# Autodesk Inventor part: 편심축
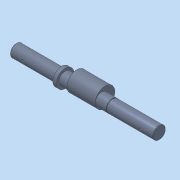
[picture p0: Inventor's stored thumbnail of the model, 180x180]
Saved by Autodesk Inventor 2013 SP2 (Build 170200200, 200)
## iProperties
Manager: 한국ATC센터
Company: 한국ATC센터
Created: 2014-10
Part Number: 편심축
Document SubType Name: Modeling
Designer: 한국ATC센터
Density: 7.86 g/cm^3
Material: 강, 연강
Mass: 1420.77 g
Surface Area: 286.546 cm^2
Volume: 180.76 cm^3
Author: KYOUNG IL JANG
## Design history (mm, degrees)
sketch "스케치1"
  geometry: L1 (-142, 0)-(142, 0); L2 (-142, 0)-(-142, 12.5); L3 (-142, 12.5)-(-52, 12.5); L4 (-52, 12.5)-(-52, 17.5); L5 (-52, 17.5)-(-45, 17.5); L6 (-45, 17.5)-(-45, 12.5); L7 (-45, 12.5)-(48.65, 12.5); L8 (48.65, 12.5)-(48.65, 11.95); L9 (48.65, 11.95)-(50, 11.95); L10 (50, 11.95)-(50, 12.5); L11 (50, 12.5)-(142, 12.5); L12 (142, 12.5)-(142, 0); L13 (109, 12.5)-(109, 9.1); L14 (109, 9.1)-(134, 9.1); L15 (134, 9.1)-(134, 12.5); L16 (117, -12.5)-(119.5, -12.5); L17 (119.5, -12.5)-(117, -10); L18 (117, -10)-(117, -12.5); L19 (-109, 12.5)-(-109, 9.1); L20 (-109, 9.1)-(-134, 9.1); L21 (-134, 9.1)-(-134, 12.5); L22 (-117, -12.5)-(-117, -10); L23 (-117, -10)-(-114.5, -12.5); L24 (-114.5, -12.5)-(-117, -12.5); 2 further points
  constraints: 48 end point, 11 parallel, 8 perpendicular, 5 collinear, 4 point on line, 1 coincident, 1 horizontal, 1 midpoint, 1 vertical
  dimensions: "d0" = 284 distance of L1.start L1.end (derived); "d1" = 25 diameter of L3 L1; "d2" = 35 diameter of L5 L1; "d3" = 90 distance of L2.end L3.end; "d4" = 187 distance between parallel lines of L12 L6; "d6" = 1.35 distance of L8.end L9.end; "d7" = 23.9 diameter of L9 L1; "d8" = 3.4 distance between parallel lines of L14 L11; "d9" = 8 distance between parallel lines of L15 L12; "d10" = 25 distance of L13.end L14.end; "d11" = 25 diameter of L16 L1 (= d1); "d12" = 25 distance from line of L12 L16.start; "d13" = 45 deg angle of L17 L18; "d14" = 5 diameter of L16.end L18; "d27" = 92 distance between parallel lines of L10 L12; "d32" = 7 distance of L4.end L5.end; "d33" = 8 distance between parallel lines of L2 L21; "d34" = 25 distance between parallel lines of L21 L19; "d35" = 3.4 distance between parallel lines of L3 L20; "d36" = 25 distance from line of L22.start L2; "d37" = 5 diameter of L23.end L22
revolve "회전1" stored, may be unused: angle "d15" = 90 deg
revolve "회전2" stored, may be unused: angle "d16" = 90 deg
revolve "회전3" stored, may be unused: angle "d38" = 90 deg
extrude "돌출1" cut sketch "스케치1" stored distance "d17" = 8; taper "d18" = 0 deg
fillet "모깎기1" dims "d19" = 4
node "작업 평면1"
sketch "스케치2"
  geometry: L1 (12.99, -6.5)-(8.66, -14); L2 (-12.99, -6.5)-(-8.66, -14); C1 r 12.5 at (0, 0) reference; C2 r 19.5 at (0, 7); A1 r 15 centre (0, 1) between (12.99, -6.5) and (-12.99, -6.5); A2 r 10 centre (0, -9) between (-8.66, -14) and (8.66, -14); 1 further point
  constraints: 5 tangent, 4 end point, 4 point on circle, 3 centre point, 3 vertical alignment
  dimensions: "d21" = 7 distance of point (0, 0) C2.centre; "d30" = 39 diameter of C2 (derived); "d39" = 10 distance of A2.centre A1.centre; "d40" = 30 diameter of A1; "d41" = 20 diameter of A2; "d42" = 1 distance of point (0, 0) A1.centre
extrude "돌출2" join sketch "스케치2" distance "d22" = 56; taper "d23" = 0 deg
chamfer "모따기1" distance "d24" = 1; stored, may be unused: second distance "d25" = 2, angle "d26" = 45 deg
node "솔리드1"
other parameters: "d20" = 16
